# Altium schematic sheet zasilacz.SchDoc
size A3
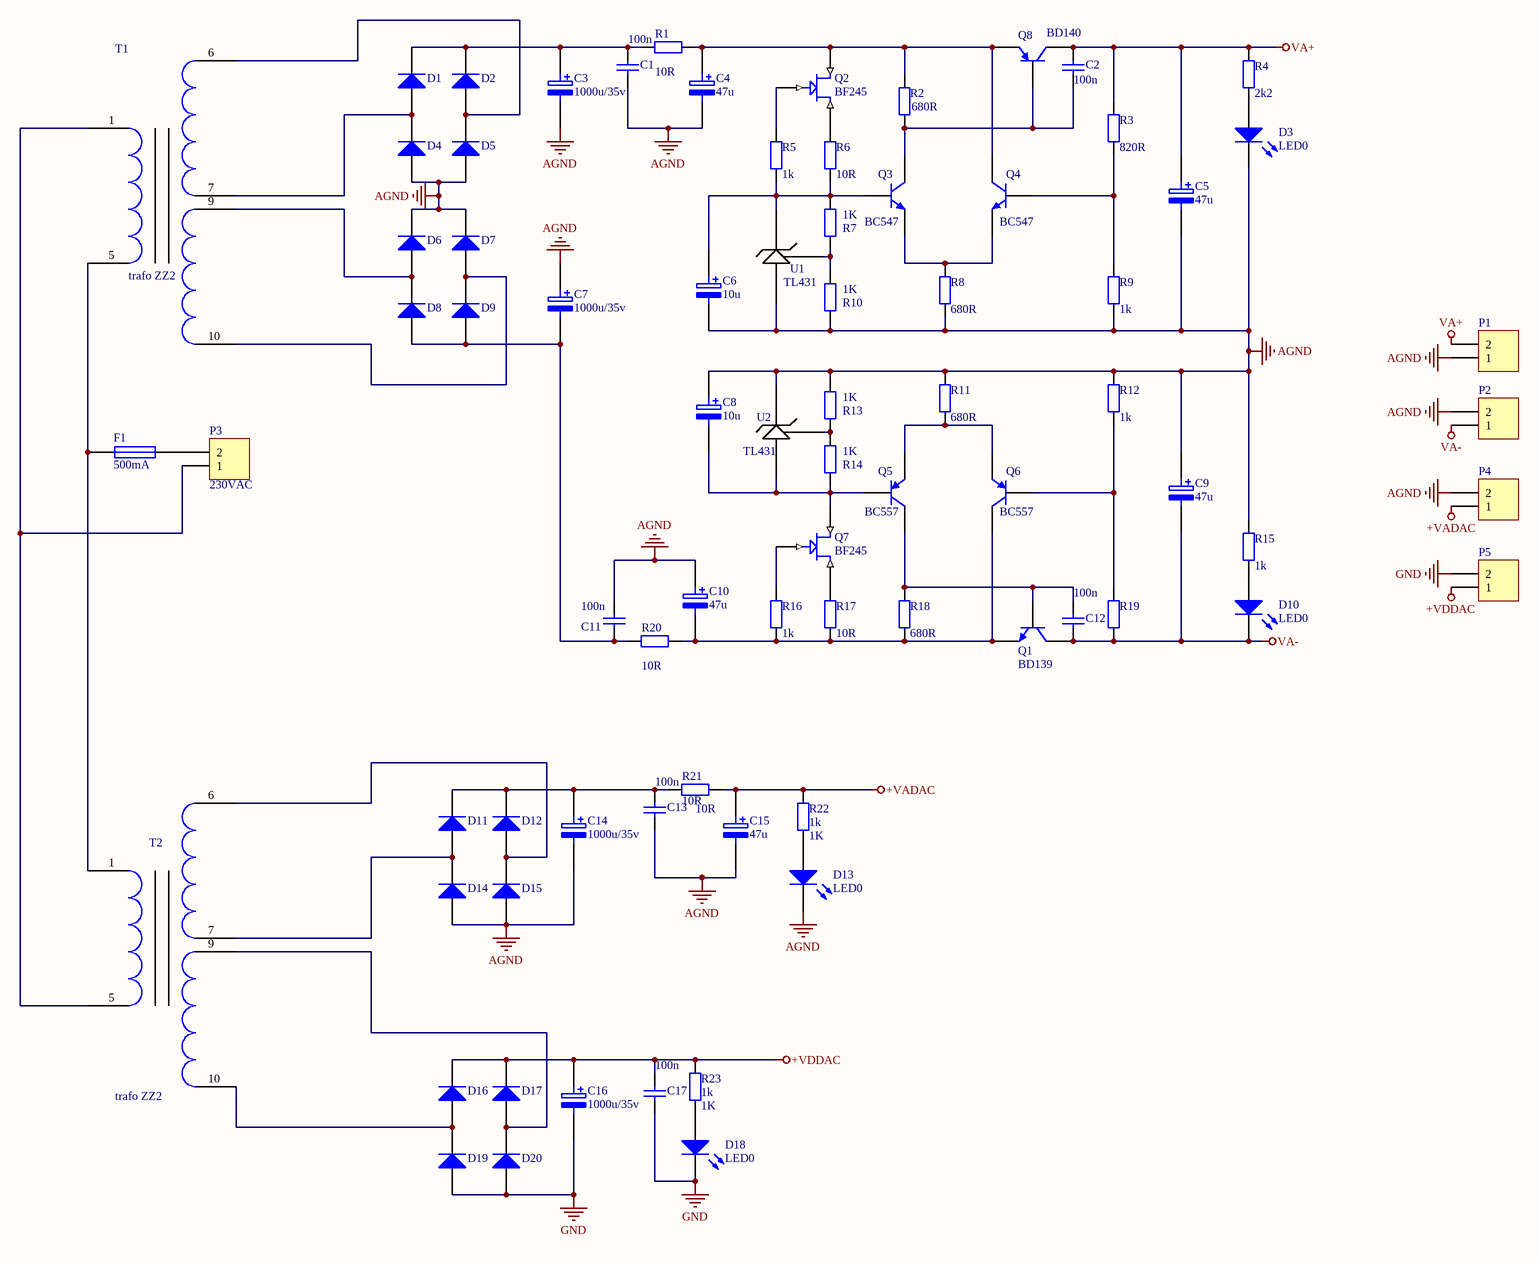
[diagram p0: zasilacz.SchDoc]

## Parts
C1  value 100n  [1206]
C2  100n  [1206]
C3  1000u/35v  [1000u/35v]
C4  47u  [47u/25v]
C5  47u  [47u/25v]
C6  10u  [10uf/25v]
C7  1000u/35v  [1000u/35v]
C8  10u  [10uf/25v]
C9  47u  [47u/25v]
C10  47u  [47u/25v]
C11  100n  [1206]
C12  100n  [1206]
C13  value 100n  [1206]
C14  1000u/35v  [1000u/35v]
C15  47u  [47u/25v]
C16  1000u/35v  [1000u/35v]
C17  value 100n  [1206]
D1  (no value)  [diode0.4]
D2  (no value)  [DIODE0.4]
D3  LED0  [1206]
D4  (no value)  [DIODE0.4]
D5  (no value)  [DIODE0.4]
D6  (no value)  [DIODE0.4]
D7  (no value)  [DIODE0.4]
D8  (no value)  [DIODE0.4]
D9  (no value)  [DIODE0.4]
D10  LED0  [1206]
D11  (no value)  [DIODE0.4]
D12  (no value)  [DIODE0.4]
D13  LED0  [1206]
D14  (no value)  [DIODE0.4]
D15  (no value)  [DIODE0.4]
D16  (no value)  [DIODE0.4]
D17  (no value)  [DIODE0.4]
D18  LED0  [1206]
D19  (no value)  [DIODE0.4]
D20  (no value)  [DIODE0.4]
F1  500mA  [BEZP_OKR]
P1  (no value)  [wago]
P2  (no value)  [wago]
P3  230VAC  [wago]
P4  (no value)  [wago]
P5  (no value)  [wago]
Q1  BD139  [TO-126]
Q2  BF245  [TO-226-AA]
Q3  BC547  [to-92]
Q4  BC547  [to-92]
Q5  BC557  [TO-92]
Q6  BC557  [TO-92]
Q7  BF245  [TO-226-AA]
Q8  BD140  [TO-126]
R1  10R  [1206]
R2  680R  [1206]
R3  820R  [1206]
R4  2k2  [1206]
R5  1k  [1206]
R6  10R  [1206]
R7  1k  [1206]
R8  680R  [1206]
R9  1k  [1206]
R10  1k  [1206]
R11  680R  [1206]
R12  1k  [1206]
R13  1k  [1206]
R14  1k  [1206]
R15  value 1k  [1206]  (hidden comment: 2k2)
R16  1K  [1206]
R17  10R  [1206]
R18  680R  [1206]
R19  820R  [1206]  (value not drawn)
R20  10R  [1206]
R21  10R  [1206]
R22  1k  [1206]
R23  1k  [1206]
T1  trafo ZZ2  [TRAFO ZZ7]
T2  trafo ZZ2  [TRAFO ZZ7]
U1  TL431  [sot23-3]
U2  TL431  [sot23-3]

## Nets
+VADAC: C15.1 P4.1 R21.1 R22.1
+VDDAC: C16.1 C17.1 D16.2(K) D17.2(K) P5.1 R23.1
AGND: C1.2 C3.2 C4.2 C5.2 C6.2 C7.1 C8.1 C9.1 C10.1 C11.1 C13.2 C14.2 C15.2 D3.2(K) D4.1(A) D5.1(A) D6.2(K) D7.2(K) D13.2(K) D14.1(A) D15.1(A) P1.1 P2.2 P4.2 R8.2 R9.2 R10.2 R11.1 R12.1 R13.1 R15.1 U1.3(A) U2.1(K)
GND: C16.2 C17.2 D18.2(K) D19.1(A) D20.1(A) P5.2
VA+: C2.1 C5.1 P1.2 Q8.1(C) R3.1 R4.1
VA-: C9.2 C12.2 D10.2(K) P2.1 Q1.2(B) R19.2
NetC1_1: C1.1 C3.1 D1.2(K) D2.2(K) R1.2
NetC2_2: C2.2 Q3.1(C) Q8.2(B) R2.2
NetC4_1: C4.1 Q2.2(D) Q4.1(C) Q8.3(E) R1.1 R2.1
NetC6_1: C6.1 Q3.2(B) R5.2 R6.2 R7.1 U1.1(K)
NetC7_2: C7.2 C11.2 D8.1(A) D9.1(A) R20.2
NetC8_2: C8.2 Q5.2(B) Q7.2(D) R14.2 U2.3(A)
NetC10_2: C10.2 Q1.1(C) Q6.1(C) R16.2 R17.2 R18.2 R20.1
NetC12_1: C12.1 Q1.3(E) Q5.1(C) R18.1
NetC13_1: C13.1 C14.1 D11.2(K) D12.2(K) R21.2
NetD1_1: D1.1(A) D4.2(K) T1.7
NetD2_1: D2.1(A) D5.2(K) T1.6
NetD3_1: D3.1(A) R4.2
NetD6_1: D6.1(A) D8.2(K) T1.9
NetD7_1: D7.1(A) D9.2(K) T1.10
NetD10_1: D10.1(A) R15.2
NetD11_1: D11.1(A) D14.2(K) T2.7
NetD12_1: D12.1(A) D15.2(K) T2.6
NetD13_1: D13.1(A) R22.2
NetD16_1: D16.1(A) D19.2(K) T2.10
NetD17_1: D17.1(A) D20.2(K) T2.9
NetD18_1: D18.1(A) R23.2
NetF1_1: F1.1 P3.2
NetF1_2: F1.2 T1.5 T2.1
NetP3_1: P3.1 T1.1 T2.5
NetQ2_1: Q2.1(G) R5.1
NetQ2_3: Q2.3(S) R6.1
NetQ3_3: Q3.3(E) Q4.3(E) R8.1
NetQ4_2: Q4.2(B) R3.2 R9.1
NetQ5_3: Q5.3(E) Q6.3(E) R11.2
NetQ6_2: Q6.2(B) R12.2 R19.1
NetQ7_1: Q7.1(G) R16.1
NetQ7_3: Q7.3(S) R17.1
NetR7_2: R7.2 R10.1 U1.2(REF)
NetR13_2: R13.2 R14.1 U2.2(REF)

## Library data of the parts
C1 C2 C11-C13 C17 = Cap: Capacitor
C3-C10 C14-C16 = ELECTRO2: Electrolytic Capacitor
D1 D2 D4-D9 D11 D12 D14-D17 D19 D20 = Diode 1N4007: 1 Amp General Purpose Rectifier
D3 D10 D13 D18 = LED0: Typical INFRARED GaAs LED
F1 = Fuse 1: Fuse
P1-P5 = Header 2: Header, 2-Pin
Q1 Q3 Q4 = NPN: NPN Bipolar Transistor
Q2 Q7 = JFET N
Q5 Q6 Q8 = PNP: PNP Bipolar Transistor
R1-R23 = Res2: Resistor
